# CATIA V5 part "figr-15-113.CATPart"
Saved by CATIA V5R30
Part number: Part1
Bounding box of the stored display mesh (mm): x -55.37 to 68.649, y -21.457 to 35.984, z 0 to 57.441
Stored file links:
  D:\PROJECTS\CATIA V56R 2020\Resources\Parts File\c15_catia_v5_6r2020_prt\figr-15-113.CATPart
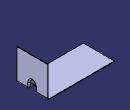
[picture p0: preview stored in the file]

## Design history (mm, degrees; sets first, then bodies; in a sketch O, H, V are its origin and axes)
SheetMetalParameters1: Thickness 1, BendRadius 2, KFactor 0.400515 {= log(min(100,max(20*SheetMetalParameters1.BendRadius,SheetMetalParameters1.Thickness)/SheetMetalParameters1.Thickness))/log(100)/2}, ReliefRadialLength 1, ReliefAxialLength 2, MinimumBendRadius 0
Body1 (main body)
  Sketch1 on xy-plane, origin (0, 0, 0), H (1, 0, 0), V (0, 1, 0)
    line L1 (-55.3695, 35.9836) -> (67.649, 35.9836)
    line L2 (67.649, 35.9836) -> (67.649, -21.4575)
    line L3 (67.649, -21.4575) -> (-55.3695, -21.4575)
    line L4 (-55.3695, -21.4575) -> (-55.3695, 35.9836)
    horizontal: L1 H, L3 H
    vertical: L2 V, L4 V
  Wall1: Thickness 1, Profile Sketch1
  d_NewWallOnEdge1: NewWallOnEdge_Edge edge [face of Wall1 | face of Wall1], NewWallOnEdge_Length 57.4411, NewWallOnEdge_HeightLimitOffset 0, NewWallOnEdge_WidthOffset1 0, NewWallOnEdge_WidthOffset2 0, NewWallOnEdge_Angle 90, NewWallOnEdge_BendRadiusValue 2 {= SheetMetalParameters1.BendRadius}, NewWallOnEdge_BendTable SheetMetalParameters1, KFacteur 0.400515 {= log(min(100,max(20*d_NewWallOnEdge1.Radius,SheetMetalParameters1.Thickness)/SheetMetalParameters1.Thickness))/log(100)/2}
  Sketch2 on , origin (67.7759, 6.9809, 0.8843), H (0.7052, 0, 0.709), V (0, -1, 0)
    point P1 (0, 0)
  d_Stamp1: Stamp_FilletRadius 2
